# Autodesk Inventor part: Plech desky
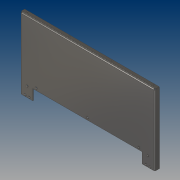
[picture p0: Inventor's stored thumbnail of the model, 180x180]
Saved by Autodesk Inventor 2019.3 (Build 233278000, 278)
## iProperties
Created: 2019-02
Part Number: Plech desky
Material: Nerezová ocel
Document SubType Name: Plech
Designer: B-hon
Density: 8 g/cm^3
Sheet Metal Rule: Výchozí_mm
Appearance: Ocel – leštěná
Author: B-hon
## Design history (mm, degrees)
node "Plocha1"
  sketch "Náčrt1"
    geometry: L1 (65, 0)-(635, 0) reference; L2 (700, 325)-(0, 325); L3 (65, 0)-(65, -45); L4 (65, -45)-(0, -45) reference; L5 (700, -45)-(635, -45) reference; L6 (635, -45)-(635, 0); L7 (0, 325)-(0, -45); L8 (700, 325)-(700, -45); 2 further points
    constraints: 16 end point, 4 horizontal, 2 vertical, 1 midpoint, 1 parallel, 1 other
    dimensions: "d1" = 325 distance of L2.end point (0, 0)
node "Obruba1"
node "Upravit přímo1"
sketch "Náčrt6"
  geometry: L1 (65, -5)-(65, -45) reference; L2 (65, -45)-(0, -45) reference; 4 further points
  constraints: 1 horizontal alignment
  dimensions: "d71" = 21 distance of point (46, -38) point (25, -38); "d72" = 19 distance from line of L1 point (46, -38); "d73" = 7 distance from line of L2 point (46, -38); "d74" = 10.5 horizontal distance of point (46, -38) point (35.5, 7); "d75" = 52 distance from line of L2 point (35.5, 7)
hole "Díra4" sketch "Náčrt6" at (25, -38), (46, -38), (35.5, 7) diameter "d76" = 5.5; stored, may be unused: countersink angle "d80" = 90 deg, drill point angle "d82" = 118 deg; dims "d77" = 6, "d78" = 10.5, "d79" = 2, "d81" = 3 (= Tloušťka)
pattern_linear "Obdélníkové pole5" dims "d85" = 629
node "Obruba2"
node "Obruba3"
sketch "Náčrt13"
  geometry: L1 (0, 0)-(700, 0) reference; L2 (0, -16.5)-(0, 0) reference; 2 further points
  dimensions: "d137" = 6.25 distance from line of L1 point (20, -6.25) (computed from d164); "d138" = 20 distance from line of point (20, -6.25) L2; "d164" = 16.5 distance of L2.start L1.start (derived)
hole "Díra7" sketch "Náčrt13" at (20, -6.25) diameter "d139" = 5.5; stored, may be unused: countersink angle "d143" = 90 deg, drill point angle "d145" = 0 deg; dims "d140" = 6, "d141" = 9.5, "d142" = 2, "d144" = 3 (= Tloušťka)
pattern_linear "Obdélníkové pole7" dims "d148" = 220
node "Upravit přímo2"
sketch "Náčrt14"
  geometry: L1 (6, 319)-(6, -45) reference; L2 (65, -45)-(6, -45) reference; L3 (65, 10)-(65, -45) reference; L4 (635, 10)-(65, 10) reference; L5 (635, -45)-(635, 10) reference; L6 (694, -45)-(635, -45) reference; L7 (694, -45)-(694, 319) reference; L8 (694, 319)-(6, 319) reference; C1 r 5.25 at (35.5, 7) reference; C2 r 5.25 at (25, -38) reference; C3 r 5.25 at (46, -38) reference; C4 r 5.25 at (654, -38) reference; C5 r 5.25 at (664.5, 7) reference; C6 r 5.25 at (675, -38) reference; 4 further points
  constraints: 2 horizontal alignment
  dimensions: "d152" = 535 distance of point (617.5, 21) point (82.5, 21); "d153" = 570 distance of L4.start L3.start (derived); "d154" = 17.5 distance from line of point (82.5, 21) L3 (= -0.5 x d152 + 0.5 x d153); "d155" = 267.5 distance of point (350, 21) point (82.5, 21) (= 0.5 x d152); "d156" = 11 distance from line of L4 point (82.5, 21)
hole "Díra8" sketch "Náčrt14" at (82.5, 21), (350, 21), (617.5, 21) diameter "d157" = 5.5; stored, may be unused: countersink angle "d161" = 90 deg, drill point angle "d163" = 118 deg; dims "d158" = 6, "d159" = 10.5, "d160" = 2, "d162" = 3 (= Tloušťka)
node "Těleso1"
feature "Deska1" dims "d8" = 3 (= Tloušťka)
sketch "Náčrt2"
  geometry: L1 through (350, 0) direction (-1, 0); L2 through (0, -11.25) direction (0, -1); L3 (0, -22.5)-(700, -22.5); L4 (700, -22.5)-(700, 0)
  constraints: 6 end point, 1 horizontal, 1 perpendicular, 1 vertical
feature "Deska2" dims "d8" = 3 (= Tloušťka), "d9" = 3 (= ŠířkaVýštipu), "d10" = 1.5 (= HloubkaVýštipu), "d11" = 6 (= MinimálníZbytek), "d12" = 3 (= PřechodovýPoloměr), "d13" = 22.5, "d14" = 90 deg, "d15" = 3 (= PoloměrOhybu), "d16" = 12 (= VelikostRohovéhoVýštipu), "d17" = 3 (= VelikostMezery), "d18" = 3 (= VelikostJacobihoPoloměru), "MezeraVystřižení" = 0.01
feature "Ohyb1" dims "d8" = 3 (= Tloušťka), "d9" = 3 (= ŠířkaVýštipu), "d10" = 1.5 (= HloubkaVýštipu), "d11" = 6 (= MinimálníZbytek), "d12" = 3 (= PřechodovýPoloměr), "d13" = 22.5, "d14" = 90 deg, "d15" = 3 (= PoloměrOhybu), "MezeraVystřižení" = 0.01
feature "Roh1" dims "d13" = 22.5, "d14" = 90 deg, "d16" = 12 (= VelikostRohovéhoVýštipu), "d17" = 3 (= VelikostMezery), "d18" = 3 (= VelikostJacobihoPoloměru)
sketch "Náčrt10"
  geometry: L1 through (182, 0) direction (-1, 0); L2 through (0, -12.5) direction (0, -1); L3 (0, -25)-(364, -25); L4 (364, -25)-(364, 0)
  constraints: 6 end point, 1 horizontal, 1 perpendicular, 1 vertical
feature "Deska3" dims "d8" = 3 (= Tloušťka), "d106" = 3 (= ŠířkaVýštipu), "d107" = 1.5 (= HloubkaVýštipu), "d108" = 6 (= MinimálníZbytek), "d109" = 3 (= PřechodovýPoloměr), "d110" = 25, "d111" = 90 deg, "d112" = 3 (= PoloměrOhybu), "d113" = 12 (= VelikostRohovéhoVýštipu), "d114" = 3 (= VelikostMezery), "d115" = 3 (= VelikostJacobihoPoloměru), "MezeraVystřižení" = 0.01
feature "Ohyb2" dims "d8" = 3 (= Tloušťka), "d106" = 3 (= ŠířkaVýštipu), "d107" = 1.5 (= HloubkaVýštipu), "d108" = 6 (= MinimálníZbytek), "d109" = 3 (= PřechodovýPoloměr), "d110" = 25, "d111" = 90 deg, "d112" = 3 (= PoloměrOhybu), "MezeraVystřižení" = 0.01
feature "Roh2" dims "d110" = 25, "d111" = 90 deg, "d113" = 12 (= VelikostRohovéhoVýštipu), "d114" = 3 (= VelikostMezery), "d115" = 3 (= VelikostJacobihoPoloměru)
sketch "Náčrt11"
  geometry: L1 through (182, 0) direction (-1, 2.83e-35); L2 through (0, -12.5) direction (-8.16e-33, -1); L3 (0, -25)-(364, -25); L4 (364, -25)-(364, 0)
  constraints: 6 end point, 1 horizontal, 1 perpendicular, 1 vertical
feature "Deska4" dims "d8" = 3 (= Tloušťka), "d116" = 3 (= ŠířkaVýštipu), "d117" = 1.5 (= HloubkaVýštipu), "d118" = 6 (= MinimálníZbytek), "d119" = 3 (= PřechodovýPoloměr), "d120" = 25, "d121" = 90 deg, "d122" = 3 (= PoloměrOhybu), "d123" = 12 (= VelikostRohovéhoVýštipu), "d124" = 3 (= VelikostMezery), "d125" = 3 (= VelikostJacobihoPoloměru), "MezeraVystřižení" = 0.01
feature "Ohyb3" dims "d8" = 3 (= Tloušťka), "d116" = 3 (= ŠířkaVýštipu), "d117" = 1.5 (= HloubkaVýštipu), "d118" = 6 (= MinimálníZbytek), "d119" = 3 (= PřechodovýPoloměr), "d120" = 25, "d121" = 90 deg, "d122" = 3 (= PoloměrOhybu), "MezeraVystřižení" = 0.01
feature "Roh3" dims "d120" = 25, "d121" = 90 deg, "d123" = 12 (= VelikostRohovéhoVýštipu), "d124" = 3 (= VelikostMezery), "d125" = 3 (= VelikostJacobihoPoloměru)
node "Promítnutá smyčka1"
feature "Posunout1" dims "d56" = 5
feature "Posunout2" dims "d151" = -15
other parameters: "Tloušťka" = 3 (derived), "KSoučinitel" = 4.4, "PoloměrOhybu" = 3 (= Tloušťka), "ŠířkaVýštipu" = 3 (= Tloušťka), "HloubkaVýštipu" = 1.5 (= 0.5 x Tloušťka), "VelikostRohovéhoVýštipu" = 12 (= 4 x Tloušťka), "MinimálníZbytek" = 6 (= 2 x Tloušťka), "PřechodovýPoloměr" = 3 (= PoloměrOhybu), "VelikostJacobihoPoloměru" = 3 (= PoloměrOhybu), "VelikostMezery" = 3 (= Tloušťka), "d54" = 0, "d55" = 0, "d149" = 0, "d150" = 0
